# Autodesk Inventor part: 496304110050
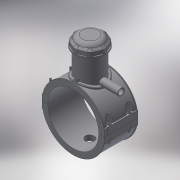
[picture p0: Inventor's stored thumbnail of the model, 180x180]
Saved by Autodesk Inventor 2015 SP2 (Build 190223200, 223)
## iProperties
Created: 2017-07
Part Number: 496304110050
Material: Generic
Description: PLASSON TAPPING SADDLE 110x50
Document SubType Name: Modeling
Designer: KIM
Mass: 840.358 g
Surface Area: 2001.37 cm^2
Volume: 840.358 cm^3
Density: 1 g/cm^3
Appearance: Default
Author: KIM
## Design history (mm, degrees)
derived "496304.ipt"
feature "Solid1::496304.ipt"
feature "Solid2::496304.ipt"
feature "Solid4::496304.ipt"
feature "Solid5::496304.ipt"
tag "TaggingFeature1"
body "Solid1"
body "Solid2"
other parameters: "d2" = 148, "d3" = 27.5, "d4" = 118, "d5" = 0, "d6" = 0.1, "d8" = 0, "d19" = 6, "d20" = 6, "d21" = 70.8, "d23" = 0, "d24" = 35.4, "d26" = 0, "d29" = 3, "d30" = 36.66667, "d31" = 6, "d32" = 0, "d33" = 0, "d34" = 0.6, "d40" = 68.64, "d41" = 66, "d43" = 0, "d45" = 0, "d47" = 136.8, "d70" = 15, "d72" = 0, "d73" = 6, "d75" = 5, "d76" = 0, "d77" = 5.5, "d78" = 85, "d79" = 15, "d80" = 47.2, "d82" = 5 deg, "d84" = 4, "d85" = 14, "d86" = 0, "d87" = 3, "d88" = 0, "d89" = 1, "d90" = 1, "d91" = 94.4, "d92" = 0, "d93" = 0.5, "d94" = 57.89474, "d96" = 134.64, "d97" = 2.36, "d98" = 0, "d102" = 1.1, "d120" = 140 deg, "d121" = 24.228, "d122" = 20 deg, "d123" = 264, "d124" = 79.2, "d126" = 0, "d143" = 113.3, "d145" = 16.92308, "d149" = 1.65, "d150" = 18.61538, "d153" = 118, "d154" = 0, "d156" = 66, "d157" = 160 deg, "d159" = 4.4, "d161" = 1.65, "d162" = 70.8, "d163" = 0, "d164" = 55, "d167" = 11, "d168" = 64.39024, "d170" = 3.375, "d172" = 0, "d173" = 1, "d175" = 55, "d176" = 20 deg, "d177" = 7.7, "d178" = 22, "d180" = 0, "d183" = 8.8, "d184" = 6.16, "d185" = 38.35, "d186" = 38.35, "d187" = 66, "d188" = 6.6, "d189" = 7.7, "d190" = 0, "d191" = 99, "d193" = 6.3, "d194" = 4.13, "d195" = 90 deg, "d197" = 0, "d199" = 0, "d200" = 11, "d202" = 0, "d203" = 177, "d204" = 62.7, "d205" = 46.2, "d206" = 56.1, "d207" = 132.75, "d208" = 138.06, "d209" = 164.61, "d210" = 56.76, "d211" = 66, "d212" = 52.8, "d213" = 35.1, "d216" = 0, "d217" = 11, "d218" = 11, "d219" = 2.2, "d224" = 0, "d230" = 4.4, "d233" = 6, "d236" = 74, "d237" = 35.4, "d238" = 6.02433, "d240" = 35.4, "d241" = 35.4, "d242" = 35.4, "d243" = 6, "d244" = 35.4, "d245" = 35.4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
